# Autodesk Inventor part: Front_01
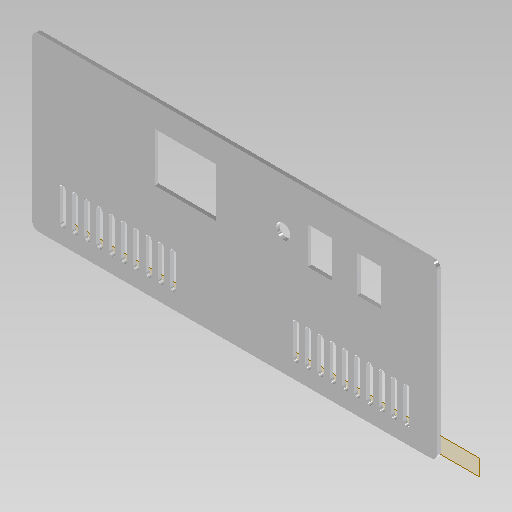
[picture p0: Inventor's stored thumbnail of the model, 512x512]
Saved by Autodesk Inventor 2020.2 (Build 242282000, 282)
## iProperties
Created: 2014-09
Part Number: Front_01
Material: Aluminium 6061
Document SubType Name: Modeling
Designer: F.Stasiak
Density: 2.7 g/cm^3
Appearance: Aluminium - płaski
Catalog Web Link: www.expertbooks.pl
Manager: www.cadconsulting.pl
Company: Fabian Stasiak CAD Consulting
Author: F.Stasiak
Subject: Zbiór ćwiczeń. Autodesk Inventor 2020. Kurs Professional
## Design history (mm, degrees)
node "Płaszczyzna konstrukcyjna1"
sketch "Szkic1"
  geometry: L1 (-196.945, 128.034)-(133.055, 128.034); L2 (133.055, 128.034)-(133.055, -11.966); L3 (133.055, -11.966)-(-196.945, -11.966); L4 (-196.945, -11.966)-(-196.945, 128.034); 3 further points
  constraints: 8 end point, 2 midpoint, 2 parallel, 1 horizontal, 1 horizontal alignment, 1 perpendicular, 1 vertical alignment
  dimensions: "d0" = 330 distance of L2.end L3.end; "d1" = 140 distance of L1.end L2.end
extrude "Wyciągnięcie proste1" new body sketch "Szkic1" distance "d2" = 3; taper "d3" = 0 deg
fillet "Zaokrąglenie1" dims "d4" = 5
sketch "Szkic2"
  geometry: L1 (-87.724, 103.012)-(-67.724, 103.012); L2 (-67.724, 103.012)-(-67.724, 73.012); L3 (-67.724, 73.012)-(-87.724, 73.012); L4 (-87.724, 73.012)-(-87.724, 103.012); L5 (-47.724, 103.012)-(-27.724, 103.012); L6 (-27.724, 103.012)-(-27.724, 73.012); L7 (-27.724, 73.012)-(-47.724, 73.012); L8 (-47.724, 73.012)-(-47.724, 103.012); C1 r 6 at (-7.724, 88.012); 1 further point
  constraints: 16 end point, 4 parallel, 2 horizontal, 2 perpendicular, 2 point on line, 1 centre point
  dimensions: "d22" = 20 distance of L1.start L1.end; "d23" = 30 distance of L1.end L2.end; "d24" = 20 distance of L5.start L5.end (= d22); "d25" = 20 distance between parallel lines of L8 L2; "d26" = 12 diameter of C1; "d27" = 20 distance from line of L6 C1.centre
extrude "Wyciągnięcie proste2" cut sketch "Szkic2" distance "d5" = 3; taper "d6" = 0 deg
sketch "Szkic3"
  geometry: L1 (-96.945, 108.034)-(-46.945, 108.034); L2 (-46.945, 108.034)-(-46.945, 68.034); L3 (-46.945, 68.034)-(-96.945, 68.034); L4 (-96.945, 68.034)-(-96.945, 108.034); L5 (128.055, 128.034)-(-191.945, 128.034) reference; L6 (-196.945, 123.034)-(-196.945, -6.966) reference; 1 further point
  constraints: 8 end point, 2 parallel, 1 horizontal, 1 perpendicular
  dimensions: "d8" = 40 distance of L3.end L1.start; "d9" = 50 distance of L2.end L3.end; "d10" = 100 distance between parallel lines of L4 L6; "d28" = 20 distance between parallel lines of L5 L1
extrude "Wyciągnięcie proste3" cut sketch "Szkic3" extent not by distance; stored distance "d11" = 3; taper "d12" = 0 deg
sketch "Szkic4"
  geometry: L1 (-171.945, 3.034)-(-171.945, 28.034); L2 (-169.445, 3.034)-(-169.445, 28.034); L3 (-174.445, 28.034)-(-174.445, 3.034); L4 (-196.945, 123.034)-(-196.945, -6.966) reference; L5 (-191.945, -11.966)-(128.055, -11.966) reference; A1 r 2.5 centre (-171.945, 3.034) between (-174.445, 3.034) and (-169.445, 3.034); A2 r 2.5 centre (-171.945, 28.034) between (-169.445, 28.034) and (-174.445, 28.034); 2 further points
  constraints: 8 end point, 4 point on circle, 4 tangent, 2 centre point, 1 midpoint, 1 parallel, 1 vertical
  dimensions: "d13" = 25 distance of L1.start L1.end; "d14" = 5 diameter of A2; "d15" = 25 distance between parallel lines of L4 L1; "d16" = 15 distance from line of L1.start L5
extrude "Wyciągnięcie proste4" cut sketch "Szkic4" extent not by distance; stored distance "d17" = 3; taper "d18" = 0 deg
pattern_linear "Szyk prostokątny1" dims "d21" = 10
mirror "Odbicie lustrzane1"
node "Bryła1"
